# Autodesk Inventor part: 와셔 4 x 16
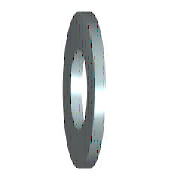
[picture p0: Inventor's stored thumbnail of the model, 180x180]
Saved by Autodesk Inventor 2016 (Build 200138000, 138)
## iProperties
IsCustomPart: 1
Created: 2012-02
Part Number: 와셔 4 x 16
Material: 강철, 연강
Description: 미터법 평면 와셔
Document SubType Name: Modeling
Standard: ANSI B18.22M
Designer: mduedu
Standard Revision: 1999
Standards Organization: ANSI
Language: ko-KR
Size Designation: 4 W
Categories: <MemberInstance><Categories><Category DisplayName="조임쇠" InternalName="e4da775c-781d-43d5-af7c-5136215cf5a6" Mnemonic="FSTN"><Category DisplayName="와셔" InternalN
Density: 1 g/cm^3
Appearance: 파란색 - 벽 페인트 - 광택
Author: mduedu
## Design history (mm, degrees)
sketch "스케치"
  geometry: C1 r 8 at (0, 0); C2 r 2.35 at (0, 0); 1 further point
  constraints: 2 centre point, 2 coincident
  dimensions: "d0" = 4.7 diameter of C2 (= SD1); "d1" = 16 diameter of C1 (= SD2)
extrude "본체" new body sketch "스케치" distance "d2" = 2.3 (= SD); taper "d3" = 0 deg
workaxis "Work Axis1"
workplane "Work Plane1"
body "Solid1"
other parameters: "SD1" = 4.7 [user parameter; used in 1 equation term], "SD2" = 16 [user parameter; used in 1 equation term], "SD" = 2.3 [user parameter; used in 1 equation term], "d4" = 0, "d5" = 0, "d6" = 0, "d7" = 0, "NND" = 4 [user parameter]
